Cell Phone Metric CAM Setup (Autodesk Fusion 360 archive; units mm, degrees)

design "Cell Phone Metric CAM Setup" references "Cell Phone Stand - Metric Assembly", "Vise"
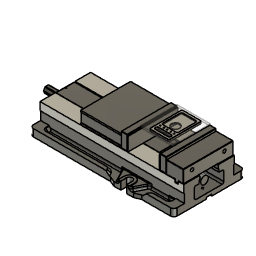
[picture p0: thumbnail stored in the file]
external_derived "ExternalDerived1"
align "Align1"
sketch "Sketch1" plane through (0, 0, 0) normal (0, 0, -1) x axis (1, 0, 0)
  line L1 (30, 46.5) -> (30, -46.5)
  line L2 (-26.5, 50) -> (26.5, 50)
  line L3 (-30, -46.5) -> (-30, 46.5)
  line L4 (26.5, -50) -> (-26.5, -50)
  line L5 (-23.5, 38.5) -> (-23.5, 36)
  line L6 (20, 42) -> (-20, 42)
  line L7 (23.5, 36) -> (23.5, 38.5)
  line L8 (-20, 32.5) -> (20, 32.5)
  line L9 (-50.8, -55) -> (50.8, -55)
  line L10 (-50.8, 55) -> (-50.8, -55)
  line L11 (50.8, 55) -> (-50.8, 55)
  line L12 (50.8, -55) -> (50.8, 55)
  line L13 (-50.8, 55) -> (50.8, -55)
  line L14 (50.8, 55) -> (-50.8, -55)
  arc A1 centre (26.5, -46.5) radius 3.5 clockwise from (30, -46.5) to (26.5, -50)
  arc A2 centre (26.5, 46.5) radius 3.5 clockwise from (26.5, 50) to (30, 46.5)
  arc A3 centre (-26.5, 46.5) radius 3.5 clockwise from (-30, 46.5) to (-26.5, 50)
  arc A4 centre (-26.5, -46.5) radius 3.5 clockwise from (-26.5, -50) to (-30, -46.5)
  circle C1 centre (10.5, 25) radius 2.117
  circle C2 centre (-10.5, 25) radius 2.117
  circle C3 centre (-21, 25) radius 2.117
  circle C4 centre (0, 25) radius 2.117
  circle C5 centre (21, 25) radius 2.117
  arc A5 centre (-20, 38.5) radius 3.5 clockwise from (-23.5, 38.5) to (-20, 42)
  arc A6 centre (20, 38.5) radius 3.5 clockwise from (20, 42) to (23.5, 38.5)
  arc A7 centre (20, 36) radius 3.5 clockwise from (23.5, 36) to (20, 32.5)
  arc A8 centre (-20, 36) radius 3.5 clockwise from (-20, 32.5) to (-23.5, 36)
  circle C6 centre (0, 0) radius 12.5
  point P36 (0, 0)
  point P1 (0, 0)
  point P34 (-50.8, 55)
  point P35 (50.8, 55)
  point P32 (50.8, -55)
  horizontal L9
  perpendicular L9 L10
  parallel L9 L11
  parallel L10 L12
  coincident L13 P36
  coincident L14 P36
  coincident P1 P36
  dimension "d1" distance P34 P35 = 101.6
  dimension "d2" distance P32 P35 = 110
extrude "Extrude1" new body sketch "Sketch1" profile of L9 L10 L11 L12 against normal blind 6 bodies "Stock"
component_insert "Component Insert"
position "Position1"
ground "Pin"
position "Position2"
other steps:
derived_base_feature "Derived Base Feature" bodies "Main Body"
named bodies: "Main Body", "Stock"

design "Cell Phone Stand - Metric Assembly"
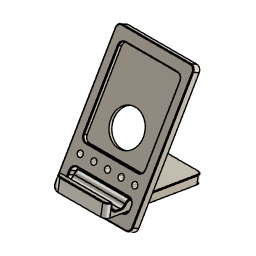
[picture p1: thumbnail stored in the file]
sketch "Main Body Sketch" plane through (0, 0, 0) normal (0, 1, 0) x axis (1, 0, 0)
  line L1 (30, 0) -> (-30, 0)
  line L2 (30, -100) -> (30, 0)
  line L3 (-30, -100) -> (30, -100)
  line L4 (-30, 0) -> (-30, -100)
  line L5 (30, -100) -> (-30, 0)
  line L6 (-30, -100) -> (30, 0)
  line L7 (23.5, -17.5) -> (-23.5, -17.5)
  line L8 (23.5, -8) -> (23.5, -17.5)
  line L9 (-23.5, -8) -> (23.5, -8)
  line L10 (-23.5, -17.5) -> (-23.5, -8)
  line L11 (0, 0) -> (0, -8)
  line L12 (23.5, -92) -> (-23.5, -92)
  line L13 (23.5, -32) -> (23.5, -92)
  line L14 (-23.5, -32) -> (23.5, -32)
  line L15 (-23.5, -92) -> (-23.5, -32)
  line L16 (0, -62.5) -> (0, -50)
  line L17 (17.2022, -62.0451) -> (0, -50)
  line L18 (21, -50) -> (0, -50)
  line L19 (17.2022, -37.9549) -> (0, -50)
  circle C1 centre (0, -50) radius 12.5
  point P6 (0, -50)
  point P1 (0, 0)
  point P11 (0, -8)
  point P12 (0, 0)
  point P17 (0, -50)
  point P21 (0, -50)
  point P22 (0, -62.5)
  point P18 (17.2022, -62.0451)
  point P23 (17.2022, -62.0451)
  point P19 (21, -50)
  point P24 (21, -50)
  point P25 (0, -50)
  point P20 (17.2022, -37.9549)
  point P26 (17.2022, -37.9549)
  point P27 (-17.2022, -62.0451)
  point P28 (-21, -50)
  point P29 (-17.2022, -37.9549)
  point P30 (0, -25)
  point P4 (30, -100)
  point P5 (-30, -100)
  point P3 (30, 0)
  point P8 (23.5, -17.5)
  point P9 (23.5, -8)
  point P7 (-23.5, -17.5)
  point P14 (23.5, -92)
  point P15 (23.5, -32)
  horizontal L1
  perpendicular L1 L2
  parallel L1 L3
  parallel L2 L4
  coincident L5 P6
  coincident L6 P6
  midpoint P1 L1
  horizontal L7
  vertical L8
  horizontal L9
  vertical L10
  midpoint L9 P11
  coincident P1 P12
  vertical L11
  horizontal L12
  vertical L13
  horizontal L14
  vertical L15
  collinear L8 L13
  collinear L10 L15
  coincident P6 P17
  coincident P6 P21
  coincident C1 P22
  vertical L16
  coincident P18 P23
  coincident P19 P24
  perpendicular L16 L18
  coincident P17 P25
  coincident P20 P26
  equal L17 L18
  equal L18 L19
  symmetric P18 L16 P27
  symmetric P19 L16 P28
  symmetric P20 L16 P29
  vertical P6 P30
  dimension "d1" distance P4 P5 = 60
  dimension "d2" distance P3 P4 = 100
  dimension "d3" distance P8 P9 = 9.5
  dimension "d4" distance L1 L9 = 8
  dimension "d5" distance P7 P8 = 47
  dimension "d6" distance L3 L12 = 8 (= "d4")
  dimension "d7" distance P14 P15 = 60
  dimension "d8" diameter C1 = 25
  dimension "d9" distance P21 P24 = 21
  dimension "d10" angle L17 L18 = 35
  dimension "d11" angle L18 L19 = 35 (= "d10")
  dimension "d12" distance P17 P30 = 25
  dimension "d15" R-Pattern1-uDistance = 21
  dimension "d16" R-Pattern1-vDistance = 0
extrude "Extrude1" new body sketch "Main Body Sketch" profile of L1 L2 L3 L4 L7 L8 L9 L10 L12 L13 L14 L15 C1 along normal blind 5.5
extrude "Extrude2" cut sketch "Main Body Sketch" profile of L12 L13 L14 L15 C1 along normal blind 3
hole "Hole2" HoleDiameter 4.234 TipAngle 118
fillet "Fillet1" radius 3.5
chamfer "Chamfer1" distance 0.5
move "Move1"
sketch "Stand Body Sketch" plane through (0, 0, 0) normal (1, 0, 0) x axis (0, 1, 0)
  line L1 (14.7999, 15.9408) -> (10.4698, 18.4408)
  line L2 (5.7198, 10.2135) -> (10.0499, 7.7135)
  line L3 (66.5456, 2.9579) -> (12.5794, 12.0948)
  line L4 (66.0448, 0) -> (66.5456, 2.9579)
  line L5 (-7.9029, 12.52) -> (66.0448, 0)
  line L6 (-6.317, 21.8867) -> (-7.9029, 12.52)
  line L7 (-2.3731, 21.2189) -> (-6.317, 21.8867)
  line L8 (-2.3281, 14.6188) -> (-2.3731, 21.2189)
  line L9 (6.5456, 13.1164) -> (-2.3281, 14.6188)
  line L10 (8.7802, 17.0486) -> (6.5456, 13.1164)
  line L11 (16.0467, 18.1003) -> (19.9906, 17.4326)
  line L12 (24.2831, 10.1133) -> (19.9906, 17.4326)
  line L13 (16.0467, 18.1003) -> (12.5794, 12.0948)
  line L14 (54.2999, 84.3568) -> (7.7999, 3.8164)
  line L15 (13.6992, 16.2157) -> (8.7802, 17.0486)
  line L16 (12.1028, 18.768) -> (11.7272, 16.5496)
  line L17 (16.0467, 18.1003) -> (12.1028, 18.768)
  line L18 (15.6711, 15.8819) -> (16.0467, 18.1003)
  line L19 (67.0881, 6.1623) -> (22.1368, 13.7729)
  line L20 (66.5456, 2.9579) -> (67.0881, 6.1623)
  circle C1 centre (13.6992, 16.2157) radius 2
  point P17 (24.2831, 10.1133)
  point P16 (16.0467, 18.1003)
  point P1 (0, 0)
  point P8 (66.0448, 0)
  point P18 (16.0467, 18.1003)
  point P5 (5.7198, 10.2135)
  point P23 (11.7272, 16.5496)
  point P26 (15.6711, 15.8819)
  point P21 (13.6992, 16.2157)
  point P22 (13.6992, 16.2157)
  point P25 (16.0467, 18.1003)
  point P28 (22.1368, 13.7729)
  point P30 (66.5456, 2.9579)
  point P7 (66.5456, 2.9579)
  point P9 (-7.9029, 12.52)
  point P10 (-6.317, 21.8867)
  point P11 (-2.3731, 21.2189)
  point P12 (-2.3281, 14.6188)
  point P13 (6.5456, 13.1164)
  point P15 (19.9906, 17.4326)
  point P14 (8.7802, 17.0486)
  point P27 (6.0499, 0.7853)
  perpendicular L3 L4
  perpendicular L5 L6
  perpendicular L6 L7
  parallel L3 L9
  coincident L3 P17
  collinear L7 L11
  perpendicular L1 L13
  coincident P16 L13
  parallel L3 L5
  horizontal P1 P8
  collinear L3 L9
  coincident P16 P18
  collinear L13 L14
  coincident P5 L5
  parallel L5 L15
  coincident C1 P23
  perpendicular L16 L17
  coincident C1 P26
  tangent C1 L18
  perpendicular L17 L18
  tangent C1 L16
  parallel L6 L16
  coincident P21 P22
  collinear L11 L17
  coincident P18 P25
  midpoint L12 P28
  perpendicular L4 L19
  coincident L3 P30
  perpendicular L3 L20
  coincident P7 P30
  dimension "d30" distance P8 P9 = 75
  dimension "d31" distance P7 P8 = 3
  dimension "d32" distance P9 P10 = 9.5
  dimension "d33" angle L11 L12 = 50
  dimension "d34" distance P10 P11 = 4
  dimension "d35" distance P12 P13 = 9
  dimension "d36" distance P15 P16 = 4
  dimension "d37" distance L9 P14 = 4.25
  dimension "d38" angle L9 L10 = 70
  dimension "d39" angle L8 L9 = 100
  dimension "d40" diameter C1 = 4
  dimension "d41" distance P8 P27 = 60
extrude "Extrude3" new body sketch "Stand Body Sketch" profile of L3 L4 L5 L6 L7 L8 L9 L10 L11 L12 L13 L14 L15 C1 L18 L19 L20 distance 40
fillet "Fillet2" radius 3.5
chamfer "Chamfer2" distance 0.5
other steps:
thread "Thread1" ThreadOffset 0 ThreadDepth 7.4
named bodies: "Main Body", "Stand Body"

design "Vise"
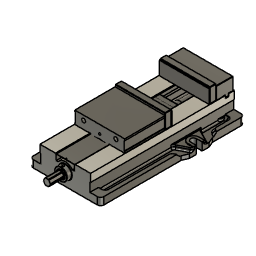
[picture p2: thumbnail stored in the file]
description: HaasClamp
base_feature "Base Feature1"
base_feature "Base Feature1"
base_feature "Base Feature1"
base_feature "Base Feature1"
base_feature "Base Feature1"
base_feature "Base Feature1"
base_feature "Base Feature1"
base_feature "Base Feature1"
base_feature "Base Feature1"
base_feature "Base Feature1"
as_built_joint "As-built1"
as_built_joint "As-built2"
as_built_joint "As-built3"
joint_origin "JointOrigin1" OffsetX 0 OffsetY 0 OffsetZ 0 AngleZ 0
joint "Assemble1" alignAngle 180 alignOffsetX 0 alignOffsetY 0 alignOffsetZ 0 (= "jaw_width_haas_050002") SlideMaximum 22.5 SlideMinimum 0
position "Position1"
sketch "Sketch1" plane through (0, -72.5, 0) normal (0, -1, 0) x axis (1, 0, 0)
  line L1 (75, 73) -> (-75, 73)
  line L2 (76, 74) -> (75, 73)
  line L3 (76, 116.5) -> (76, 74)
  line L4 (75, 117.5) -> (76, 116.5)
  line L5 (-75, 117.5) -> (75, 117.5)
  line L6 (-76, 116.5) -> (-75, 117.5)
  line L7 (-76, 74) -> (-76, 116.5)
  line L8 (-75, 73) -> (-76, 74)
  line L9 (76.4, 114.275) -> (-76, 114.275)
  line L10 (76.4, 73) -> (76.4, 114.275)
  line L11 (-76, 73) -> (76.4, 73)
  line L12 (-76, 114.275) -> (-76, 73)
  circle C1 centre (49.21, 96.8) radius 11
  circle C2 centre (-49.21, 96.8) radius 11
  point P14 (76.4, 73)
  point P12 (-76, 114.275)
  point P13 (76.4, 114.275)
  horizontal L9
  vertical L10
  horizontal L11
  vertical L12
  coincident L1 P14
  coincident L7 P12
  dimension "d16" distance P12 P13 = 152.4
  dimension "d17" distance P13 P14 = 41.275
place_component sketch "Sketch1"
extrude "Extrude1" new body sketch "Sketch1" profile of L1 L2 L3 L7 L8 C1 C2 L9 L11 L12 along normal blind 3.175
place_component sketch "Sketch1"
extrude "Extrude1" sketch "Sketch1" profile of L1 L2 L3 L7 L8 C1 C2 L9 L11 L12 blind -3.175
as_built_joint "As-built5"
as_built_joint "As-built6"
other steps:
create_component "CreateComponent1"
create_component "CreateComponent2"
create_component "CreateComponent3"
create_component "CreateComponent4"
create_component "CreateComponent5"
create_component "CreateComponent6"
create_component "CreateComponent7"
create_component "CreateComponent8"
create_component "CreateComponent9"
create_component "CreateComponent10"
joint_origin "JointOrigin10"
joint_origin "JointOrigin11"
create_component "CreateComponent11" sketch "Sketch1"
create_component "CreateComponent12" sketch "Sketch1"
